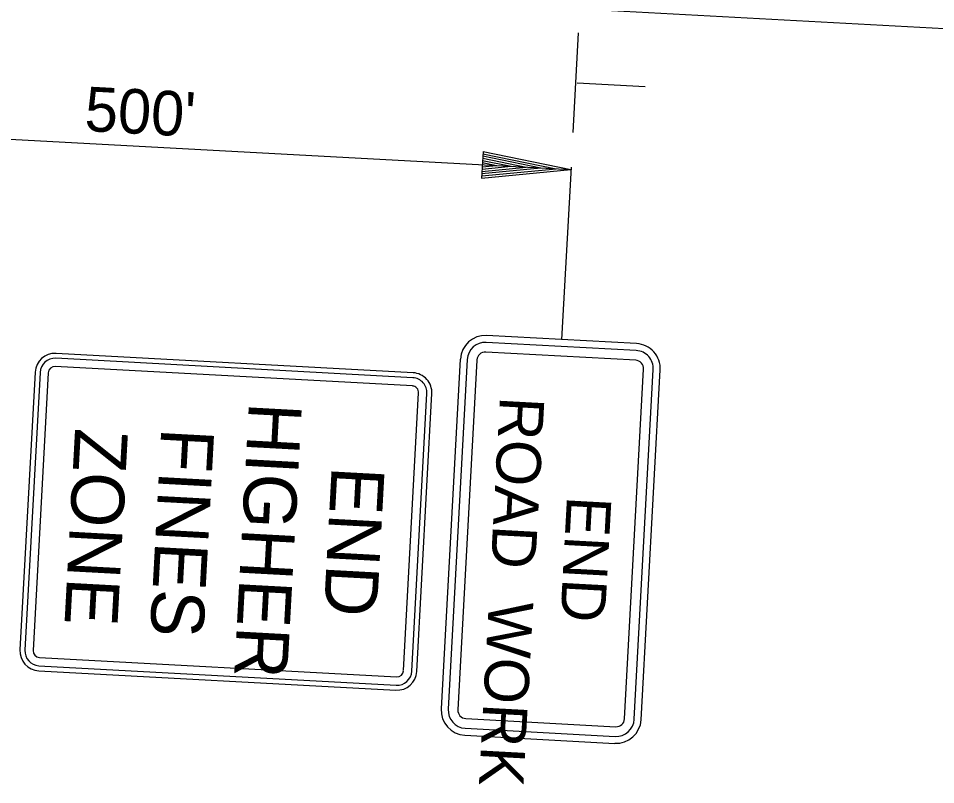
# Model space of a CAD drawing. Extents: x 879461 to 881100, y 1566470 to 1567598.
# Drawn here: x 880499.5 to 880623.3, y 1567031.7 to 1567135.1 of the extents above; entities that cross this region are included whole.
import ezdxf

# ---------------------------------------------------------------- set-up
doc = ezdxf.new("R2010")
doc.units = 0
for name, color, linetype in [('P_TC_Signs_Permanent', 7, 'Continuous'), ('P_TC_Signs_Temporary', 7, 'Continuous'), ('R_Draft', 7, 'Continuous')]:
    doc.layers.add(name, color=color, linetype=linetype)

msp = doc.modelspace()

# ---------------------------------------------------------------- linework, layer by layer
at = {"layer": 'P_TC_Signs_Permanent'}
for p, q in [((880552.79, 1567087.29), (880504.63, 1567089.91)), ((880552.75, 1567086.62), (880504.59, 1567089.24)), ((880501.8, 1567087.38), (880499.77, 1567049.92)), ((880502.47, 1567087.34), (880500.44, 1567049.88)), ((880552.69, 1567085.51), (880504.53, 1567088.13)), ((880503.59, 1567087.28), (880501.55, 1567049.82)), ((880551.5, 1567047.11), (880553.53, 1567084.57)), ((880552.61, 1567047.05), (880554.65, 1567084.51)), ((880553.28, 1567047.01), (880555.32, 1567084.47)), ((880502.33, 1567047.77), (880550.5, 1567045.15)), ((880502.39, 1567048.88), (880550.56, 1567046.26)), ((880502.3, 1567047.1), (880550.46, 1567044.48))]:
    msp.add_line(p, q, dxfattribs=at)
for centre, radius, start, end in [((880504.48, 1567087.23), 2.68, 86.8871, 176.8871), ((880504.48, 1567087.23), 2.01, 86.8871, 176.8871), ((880504.48, 1567087.23), 0.893, 86.8871, 176.8871), ((880552.64, 1567084.61), 2.01, 356.8871, 86.8871), ((880552.64, 1567084.61), 2.68, 356.8871, 86.8871), ((880552.64, 1567084.61), 0.893, 356.8871, 86.8871), ((880502.44, 1567049.77), 2.68, 176.8871, 266.8871), ((880502.44, 1567049.77), 2.01, 176.8871, 266.8871), ((880502.44, 1567049.77), 0.893, 176.8871, 266.8871), ((880550.61, 1567047.15), 2.68, 266.8871, 356.8871), ((880550.61, 1567047.15), 2.01, 266.8871, 356.8871), ((880550.61, 1567047.15), 0.893, 266.8871, 356.8871)]:
    msp.add_arc(centre, radius, start, end, dxfattribs=at)
at = {"layer": 'P_TC_Signs_Temporary'}
for p, q in [((880582.92, 1567091.22), (880562.7, 1567092.32)), ((880582.87, 1567090.29), (880562.65, 1567091.39)), ((880582.8, 1567088.98), (880562.58, 1567090.08)), ((880559.15, 1567089.14), (880556.58, 1567041.96)), ((880560.09, 1567089.08), (880557.52, 1567041.9)), ((880561.4, 1567089.01), (880558.83, 1567041.83)), ((880581.3, 1567040.61), (880583.86, 1567087.79)), ((880582.61, 1567040.54), (880585.17, 1567087.72)), ((880583.54, 1567040.49), (880586.11, 1567087.67)), ((880559.89, 1567040.65), (880580.11, 1567039.55)), ((880559.82, 1567039.34), (880580.04, 1567038.24)), ((880559.77, 1567038.4), (880579.99, 1567037.3))]:
    msp.add_line(p, q, dxfattribs=at)
for centre, radius, start, end in [((880562.52, 1567088.95), 3.37, 86.8871, 176.8871), ((880562.52, 1567088.95), 2.44, 86.8871, 176.8871), ((880582.74, 1567087.85), 3.38, 356.8871, 86.8871), ((880562.52, 1567088.95), 1.13, 86.8871, 176.8871), ((880582.74, 1567087.85), 2.44, 356.8871, 86.8871), ((880582.74, 1567087.85), 1.13, 356.8871, 86.8871), ((880559.95, 1567041.77), 3.38, 176.8871, 266.8871), ((880559.95, 1567041.77), 2.44, 176.8871, 266.8871), ((880559.95, 1567041.77), 1.13, 176.8871, 266.8871), ((880580.17, 1567040.67), 3.37, 266.8871, 356.8871), ((880580.17, 1567040.67), 2.44, 266.8871, 356.8871), ((880580.17, 1567040.67), 1.13, 266.8871, 356.8871)]:
    msp.add_arc(centre, radius, start, end, dxfattribs=at)
at = {"layer": 'R_Draft'}
for p, q in [((880928.37, 1567117.15), (880495, 1567140.72)), ((880575.06, 1567133.13), (880574.33, 1567119.68)), ((880574.89, 1567126.42), (880584.07, 1567125.92)), ((880451.88, 1567121.34), (880574.07, 1567114.7)), ((880562.22, 1567117.14), (880562.02, 1567113.56)), ((880562.22, 1567117.14), (880574.07, 1567114.7)), ((880562.15, 1567115.93), (880566, 1567115.14)), ((880562.17, 1567116.24), (880568.03, 1567115.03)), ((880562.18, 1567116.54), (880570.02, 1567114.92)), ((880562.2, 1567116.84), (880572.07, 1567114.81)), ((880562.02, 1567113.56), (880574.07, 1567114.7)), ((880562.04, 1567113.85), (880572.07, 1567114.81)), ((880562.05, 1567114.16), (880570.02, 1567114.92)), ((880562.07, 1567114.46), (880568.03, 1567115.03)), ((880562.09, 1567114.76), (880566, 1567115.14)), ((880562.1, 1567115.07), (880564.01, 1567115.25)), ((880562.13, 1567115.63), (880564.01, 1567115.25)), ((880574.08, 1567115.03), (880572.81, 1567091.77))]:
    msp.add_line(p, q, dxfattribs=at)

# ---------------------------------------------------------------- texts
at = {"layer": 'P_TC_Signs_Permanent'}
for s, p in [('HIGHER', (880530.66, 1567083.4)), ('ZONE', (880507.21, 1567079.89)), ('FINES', (880518.84, 1567079.94)), ('END', (880541.82, 1567074.76))]:
    msp.add_text(s, height=7.146, rotation=266.8871, dxfattribs=at).set_placement(p)
at = {"layer": 'P_TC_Signs_Temporary'}
for s, p in [('ROAD  WORK', (880564.51, 1567084.17)), ('END', (880573.55, 1567070.73))]:
    msp.add_text(s, height=6, rotation=266.8871, dxfattribs=at).set_placement(p)
at = {"layer": 'R_Draft'}
msp.add_text("500'", height=6, rotation=356.8871, dxfattribs=at).set_placement((880508.39, 1567119.92))

doc.saveas('drawing.dxf')
